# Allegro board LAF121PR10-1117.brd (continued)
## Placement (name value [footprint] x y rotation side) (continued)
Q7  -  [2N7002K_SOT23-3]  145.89 38.31 180 top
Q9  -  [2N7002K_SOT23-3]  51.47 63.15 0 top
Q10  -  [LMBT3904LT1G_SOT23-3]  111.67 112.87 180 bottom
Q11  L2N7002DW1T1G 2N  [DMN66D0LDW-7_SOT363-6]  180.99 65.15 0 top
Q14  L2N7002DW1T1G  [DMN66D0LDW-7_SOT363-6]  45.17 95.76 0 top
Q15  DDTA144VCA-7-F-GP  [2N7002K_SOT23-3]  48.33 97.98 270 top
Q16  DDTA144VCA-7-F-GP  [2N7002K_SOT23-3]  48.33 93.98 270 top
Q17  -  [2N7002KW_SOT323-3]  46.3 93.91 90 top
Q26  L2N7002DW1T1G  [DMN66D0LDW-7_SOT363-6]  42.17 90.75 90 top
QA1  -  [LN2306LT1G_SOT23-3]  37.75 15.4 0 top
QC1  -  [MESS138W-G_SOT323-3]  129.56 92.68 0 top
QC3  DMN63D8LDW-7  [2N7002KDWH_SOT363-6]  144.55 67.14 0 top
QC27  -  [2N7002K_SOT23-3]  140.65 33.71 90 bottom
QE1  2N7002KW 1N SOT323-3  [2N7002BKW_SOT323-3]  93.76 39.66 0 top
QI1  -  [2N7002K_SOT23-3]  23.69 100.26 270 top
QI2  -  [MMBT3904_NL_SOT23-3]  24.93 116.8 180 top
QI3  L2N7002DW1T1G  [DMN66D0LDW-7_SOT363-6]  13.81 109.67 270 bottom
QS1  L2N7002DW1T1G  [DMN66D0LDW-7_SOT363-6]  206.09 34.02 90 top
QT3  -  [2N7002K_SOT23-3]  33.82 113.51 180 bottom
QT4  -  [LN2306LT1G_SOT23-3]  32.55 115.35 0 top
QT5  -  [LN2306LT1G_SOT23-3]  37.82 113.57 180 bottom
QT6  L2N7002DW1T1G  [2N7002KDWH_SOT363-6]  31.29 123.78 180 bottom
QV1  L2N7002DW1T1G  [2N7002KDWH_SOT363-6]  123.66 120.85 0 top
QW1  DII-DMN65D8LW-7~D  [SSM3K7002FU_SC70-3]  83.66 118.74 90 top
R3  0_0402_5%  [R0402_0OHM]  210.8 54.61 180 bottom
R4  0_0402_5%  [R0402_0OHM]  210.68 56.89 180 bottom
R5  0_0805_5%  [R_0805]  203.18 57.97 0 top
R6  0_0402_5%  [R_0402]  210.8 56.13 180 bottom
R7  0_0402_5%  [R_0402-NPM]  215.57 43.68 180 top
R8  0_0402_5%  [R_0402-NPM]  215.57 44.57 180 top
R9  0_0603_5%  [R_0603]  214.33 31.75 180 top
R10  0_0402_5%  [R_0402]  116.89 27.36 180 top
R11  100K_0402_5%  [R_0402]  116.11 30.91 90 bottom
R12  0_0402_5%  [R_0402]  114.32 27.36 0 top
R13  4.7K_0402_5%  [R_0402]  41.44 85.29 90 top
R14  4.7K_0402_5%  [R_0402]  40.61 85.29 90 top
R15  0_0402_5%  [R_0402]  112.67 27.36 0 top
R16  100_0603_1%  [R_0603]  110.14 32.13 0 top
R17  20K_0402_1%  [R_0402]  105.32 29.35 270 top
R18  100K_0402_5%  [R_0402]  81.31 35.61 90 bottom
R19  1K_0402_5%  [R_0402]  80.49 36.52 270 bottom
R20  0_0402_5%  [R_0402]  82.14 36.52 270 bottom
R21  0_0402_5%  [R0402_0OHM]  82.97 35.61 90 bottom
R23  47K_0402_5%  [R_0402]  126.22 111.69 180 bottom
R24  0_0402_5%  [R0402_0OHM]  38.32 95.3 90 top
R26  0_0402_5%  [R0402_0OHM]  32.09 48.26 0 top
R27  1K_0402_5%  [R_0402]  32.09 47.43 0 top
R28  4.7K_0402_5%  [R_0402]  144.36 41.46 0 top
R30  100K_0402_5%  [R_0402]  52.93 67.1 90 top
R31  2.2K_0402_5%  [R_0402]  181.91 64.19 180 top
R32  2.2K_0402_5%  [R_0402]  181.38 68 0 top
R33  18.7K_0402_1%  [R_0402]  175.42 64.52 315 bottom
R34  2K_0402_1%  [R_0402]  178.84 61.02 315 bottom
R36  10K_0402_5%  [R_0402]  31.92 72.96 180 top
R56  0_0603_5%  [R_0603]  211.46 52.05 270 top
R58  10K_0402_5%  [R_0402]  211.68 52.94 90 top
R59  100K_0402_5%  [R_0402]  217.39 62.62 270 top
R61  100K_0402_5%  [R_0402]  218.22 62.62 270 top
R63  10K_0402_5%  [R_0402]  219.05 62.62 270 top
R64  100K_0402_5%  [R_0402]  219.87 62.62 270 top
R65  2.7K_0402_1%  [R_0402]  220.7 61.7 90 top
R68  200_0402_5%  [R_0402]  15.58 131.57 0 bottom
R69  200_0402_5%  [R_0402]  15.58 132.39 0 bottom
R82  100K_0402_5%  [R_0402]  39.07 91.96 270 top
R83  100K_0402_5%  [R_0402]  42.34 93.11 0 top
R300  10K_0402_5%  [R_0402]  208.94 34.02 90 top
R438  0_0402_5%  [R_0402]  126.96 111.69 0 bottom
R700  0_0603_5%  [R_0603]  223.36 33.08 180 bottom
R701  0_0603_5%  [R_0603]  223.36 34.35 180 bottom
R702  0_0402_5%  [R_0402]  146.22 34.48 180 top
R703  0_0402_5%  [R_0402]  32.09 46.6 0 top
R704  0_0402_5%  [R_0402]  32.09 49.08 0 top
R705  0_0402_5%  [R_0402]  37.5 95.3 90 top
R800  0_0402_5%  [R_0402]  43.25 91.31 90 top
R801  0_0603_5%  [R_0603]  210.21 52.05 270 top
RA2  0_0402_5%  [R0402_0OHM]  39.35 19.17 180 top
RA7  0_0402_5%  [R_0402]  39.35 20 180 top
RA8  10K_0402_5%  [R_0402]  30.18 8.69 0 top
RA10  100K_0402_5%  [R_0402]  29.8 17.65 0 top
RA12  0_0402_5%  [R_0402]  26.89 21.13 90 top
RA13  100K_0402_5%  [R_0402]  21.13 16.25 180 top
RA14  0_0402_5%  [R_0402]  33.38 16.06 180 top
RA19  22 +-5% 0402  [R_0402]  34.25 12.38 0 top
RA22  2.2K_0402_5%  [R_0402]  16.49 14.47 180 top
RA23  2.2K_0402_5%  [R_0402]  17.36 14.47 0 top
RA24  10_0402_1%  [R_0402]  20.94 11.43 180 top
RA25  1K_0402_5%  [R_0402]  22.7 20.49 90 top
RA26  4.7K_0402_5%  [R_0402]  20.94 12.19 180 top
RA27  10_0402_1%  [R_0402]  20.94 10.66 180 top
RA28  1K_0402_5%  [R_0402]  23.53 20.49 90 top
RA29  4.7K_0402_5%  [R_0402]  20.94 12.95 180 top
RA30  0_0402_5%  [R0402_0OHM]  9.8 19.24 0 top
RA31  10K_0402_5%  [R_0402]  17.29 19.24 0 bottom
RA32  10K_0402_5%  [R_0402]  16.43 19.24 180 bottom
RA38  0_0805_5%  [R0805_0OHM]  36.17 7.6 0 top
RA41  200K_0402_1%  [R_0402]  29.75 18.52 90 top
RA43  33_0402_5%  [R_0402]  32.41 14.09 0 top
RA44  0_0402_5%  [R_0402]  32.41 13.27 0 top
RA45  10K_0402_5%  [R_0402]  28.55 22.04 270 top
RA49  1K_0402_1%  [R_0402]  29.37 21.13 90 top
RA51  0_0805_5%  [R0805_0OHM]  21.37 22.88 270 top
RA52  0_0603_5%  [R0603_0OHM]  19.91 22.28 270 top
RA53  0_0402_5%  [R0402_0OHM]  37.7 19.17 180 top
RA54  0_0402_5%  [R_0402]  27.72 22.04 270 top
RA55  33_0402_5%  [R_0402]  35.16 10.54 180 top
RA56  0_0402_5%  [R_0402]  34.32 15.73 90 top
RA57  0_0603_5%  [R_0603]  12.48 19.17 0 top
RA58  0_0402_5%  [R_0402]  36.79 20 0 top
RC1  1K_0402_5%  [R_0402]  100.67 64.96 0 top
RC2  1K_0402_5%  [R_0402]  120.89 68.45 180 top
RC3  2.2K_0402_5%  [R_0402]  129.51 93.84 90 top
RC4  4.7K_0402_5%  [R_0402]  131.94 96.2 180 top
RC5  4.7K_0402_5%  [R_0402]  210.79 47.99 90 top
RC6  1K_0402_5%  [R_0402]  124.56 91.32 270 top
RC7  1K_0402_5%  [R_0402]  126.21 91.32 270 top
RC8  1K_0402_5%  [R_0402]  125.38 91.32 270 top
RC10  1K_0402_5%  [R_0402]  128.69 88.25 90 top
RC12  300_0402_5%  [R_0402]  145.14 56.45 180 bottom
RC13  196_0402_1%  [R_0402]  144.36 73.85 0 top
RC15  300_0402_5%  [R_0402]  148.55 60.83 0 top
RC16  1K_0402_5%  [R_0402]  129.51 88.25 90 top
RC17  10K_0402_5%  [R_0402]  130.21 48.84 270 top
RC18  0_0402_5%  [R_0402]  126.21 89.16 270 top
RC19  0_0402_5%  [R_0402]  123.73 89.16 270 top
RC20  0_0402_5%  [R_0402]  125.38 89.16 270 top
RC22  0_0402_5%  [R_0402]  124.56 89.16 270 top
RC24  1K_0402_5%  [R_0402]  127.73 91.32 270 top
RC25  1K_0402_5%  [R_0402]  126.97 91.32 270 top
RC26  1K_0402_5%  [R_0402]  123.73 91.32 270 top
RC27  220_0402_5%  [R_0402]  148.55 60.07 0 top
RC28  0_0402_5%  [R_0402]  46.14 85.29 90 top
RC29  33_0402_5%  [R_0402]  106.84 117.55 270 bottom
RC30  0_0402_5%  [R_0402]  49.12 65.54 270 top
RC33  4.7K_0402_5%  [R_0402]  132.88 47.93 90 top
RC34  4.7K_0402_5%  [R_0402]  131.99 45.51 90 top
RC36  0_0402_5%  [R_0402]  130.96 45.52 0 bottom
RC39  0_0402_5%  [R0402_0OHM]  42.39 65.54 270 top
RC40  10K_0402_5%  [R_0402]  128.44 47.93 90 top
RC41  10K_0402_5%  [R_0402]  131.99 48.84 270 top
RC42  10K_0402_5%  [R_0402]  131.1 45.51 90 top
RC44  0_0402_5%  [R_0402]  108.29 121.03 0 bottom
RC46  10K_0402_5%  [R_0402]  125.76 43.23 90 top
RC47  10K_0402_5%  [R_0402]  118.72 45.78 0 top
RC48  10K_0402_5%  [R_0402]  144.36 56.38 0 top
RC49  0_0402_5%  [R_0402]  110.71 119.39 270 bottom
RC51  2K_0402_5%  [R_0402]  120.7 38.54 180 bottom
RC52  2K_0402_5%  [R_0402]  144.36 58.16 0 top
RC53  10K_0402_5%  [R_0402]  124.88 43.23 90 top
RC54  22K_0402_5%  [R_0402]  119.92 47.67 90 top
RC56  10K_0402_5%  [R_0402]  148.55 62.48 0 top
RC57  10K_0402_5%  [R_0402]  148.55 61.65 0 top
RC58  10K_0402_5%  [R_0402]  144.76 61.91 180 bottom
RC59  10K_0402_5%  [R_0402]  144.76 62.73 180 bottom
RC60  10K_0402_5%  [R_0402]  131.91 60.64 0 top
RC61  10K_0402_5%  [R_0402]  118.83 51.18 0 top
RC62  10K_0402_5%  [R_0402]  149.47 55.75 180 top
RC74  10_0402_1%  [R_0402]  119.78 39.43 0 bottom
RC94  4.7K_0402_5%  [R_0402]  145.06 69.85 0 top
RC95  4.7K_0402_5%  [R_0402]  145.27 66.04 180 top
RC96  0_0402_5%  [R0402_0OHM]  123.19 47.93 90 top
RC97  0_0402_5%  [R_0402]  145.27 61.91 180 top
RC98  1K_0402_5%  [R_0402]  133.02 33.4 180 bottom
RC99  1K_0402_5%  [R_0402]  161.93 29.85 270 top
RC102  0_0402_5%  [R_0402]  212.9 59.49 180 top
RC103  0_0402_5%  [R_0402]  212.9 60.32 180 top
RC104  1M_0402_5%  [R_0402]  218.61 50.03 180 top
RC449  22_0402_5%  [R_0402]  125.5 45.58 0 bottom
RC602  33_0402_5%  [R_0402]  126.65 43.23 90 top
RC615  10K_0402_5%  [R_0402]  123.99 47.93 90 top
RC616  0_0402_5%  [R_0402]  127.86 89.16 270 top
RC617  0_0402_5%  [R_0402]  127.03 89.16 270 top
RC618  0_0402_5%  [R_0402]  130.96 44.7 0 bottom
RC619  10K_0402_5%  [R_0402]  144.36 62.73 0 top
RC620  10K_0402_5%  [R_0402]  145.27 63.56 180 top
RC621  10K_0402_5%  [R_0402]  127.47 47.93 90 top
RC622  10K_0402_5%  [R_0402]  121.33 45.78 180 top
RC630  0_0402_5%  [R_0402]  43.21 64.63 90 top
RC631  0_0402_5%  [R_0402]  130.96 43.87 0 bottom
RC639  10K_0402_5%  [R_0402]  131.86 40.37 90 bottom
RC640  10K_0402_5%  [R_0402]  131.92 37.47 270 bottom
RC642  10K_0402_5%  [R_0402]  120.7 40.32 180 bottom
RC646  10K_0402_5%  [R_0402]  130.21 46.43 270 top
RC661  0_0402_5%  [R_0402]  131.75 43.05 180 bottom
RC663  10K_0402_5%  [R_0402]  133.7 47.93 90 top
RC664  1K_0402_5%  [R_0402]  126.65 47.93 90 top
RC680  10_0402_5%  [R_0402]  119.78 37.18 0 bottom
RC681  100K_0402_5%  [R_0402]  127.54 44.14 270 top
RC700  0_0402_5%  [R_0402]  107.67 116.63 90 bottom
RC701  0_0402_5%  [R_0402]  109.32 116.63 90 bottom
RC703  10K_0402_5%  [R_0402]  108.49 116.63 90 bottom
RC704  33_0402_5%  [R_0402]  110.14 116.63 90 bottom
RC711  10K_0402_5%  [R_0402]  129.41 45.51 90 top
RC712  10K_0402_5%  [R_0402]  129.32 48.84 270 top
RC801  10M_0402_5%  [R_0402]  144.45 32.44 90 bottom
RC902  0_0402_5%  [R_0402]  122.55 53.42 90 top
RC905  100K_0402_5%  [R_0402]  145.27 65.18 180 top
RC906  100K_0402_5%  [R_0402]  147.28 64.38 0 top
RC914  20M_0402_5%  [R_0402]  143.54 53.01 90 bottom
RC938  10K_0402_5%  [R_0402]  124.88 47.93 90 top
RC939  1M_0402_5%  [R_0402]  143.61 48.18 90 bottom
RC1672  0_0603_5%  [R_0603]  118.91 44.64 0 top
RC1689  22 +-5% 0402  [R_0402]  127.54 55.06 270 top
RC1695  10K_0402_5%  [R_0402]  124.88 45.51 90 top
RC1696  10K_0402_5%  [R_0402]  125.76 47.93 90 top
RC1697  10K_0402_5%  [R_0402]  125.76 45.51 90 top
RC1700  0_0603_5%  [R_0603]  122.72 44.53 180 top
RC1706  10K_0402_5%  [R_0402]  120.7 35.36 180 bottom
RC1707  10K_0402_5%  [R_0402]  131.87 46.35 180 bottom
RC6121  100K_0402_5%  [R_0402]  145.27 64.38 180 top
RC6122  10K_0402_5%  [R_0402]  131.1 47.93 90 top
RC6123  10K_0402_5%  [R_0402]  120.7 41.21 180 bottom
RC6124  10K_0402_5%  [R_0402]  126.65 46.43 270 top
RC6125  0_0402_5%  [R_0402]  144.83 66.8 180 bottom
RC6126  0_0402_5%  [R_0402]  136.05 27.19 270 bottom
RC6127  10K_0402_5%  [R_0402]  135.1 26.27 90 bottom
RC6128  0_0402_5%  [R0402_0OHM]  126.4 62.16 0 top
RC6129  0_0402_5%  [R0402_0OHM]  123.95 61.58 90 top
RC6130  10K_0402_5%  [R_0402]  142.5 36.1 180 bottom
RD1  1K_0402_1%  [R_0402]  73.05 67.24 0 top
RD2  1K_0402_1%  [R_0402]  70.76 67.24 0 top
RD3  1K_0402_1%  [R_0402]  60.3 67.29 90 top
RD4  1K_0402_1%  [R_0402]  58.06 67.24 0 top
RE1  0_0805_5%  [R_0805]  92.34 36.25 0 top
RE2  10K_0402_5%  [R_0402]  91.99 39.05 180 top
RE3  100K_0402_5%  [R_0402]  91.99 38.22 180 top
RE4  240_0402_1%  [R_0402]  56.57 34.6 0 bottom
RE5  100K_0402_1%  [R_0402]  51.28 85.29 90 top
RE6  0_0603_5%  [R_0603]  35.15 85.47 180 top
RE8  100K_0402_1%  [R_0402]  33.64 83.36 180 top
RE9  0_0402_1%  [R_0402]  49.56 86.2 270 top
RE11  0_0402_1%  [R_0402]  32.72 82.58 0 top
RE12  0_0402_5%  [R_0402]  32.72 76.26 0 top
RE14  33_0402_5%  [R_0402]  41.18 65.54 270 top
RE17  10K_0402_5%  [R_0402]  33.64 74.63 180 top
RE18  10K_0402_5%  [R_0402]  42.26 85.29 90 top
RE19  10K_0402_5%  [R_0402]  39.79 86.2 270 top
RE23  10K_0402_5%  [R_0402]  47.47 64.63 90 top
RE24  10K_0402_5%  [R_0402]  32.72 84.13 0 top
RE25  10K_0402_5%  [R_0402]  44.04 64.63 90 top
RE30  0_0402_5%  [R0402_0OHM]  39.4 64.63 90 top
RE31  10K_0402_5%  [R_0402]  33.64 81.66 180 top
RE35  0_0402_5%  [R0402_0OHM]  33.64 78.1 180 top
RE36  0_0402_5%  [R0402_0OHM]  48.74 85.29 90 top
RE37  0_0402_5%  [R_0402]  46.64 64.63 90 top
RE39  0_0402_5%  [R_0402]  32.72 72.96 0 top
RE40  0_0402_5%  [R_0402]  32.72 69.65 0 top
RE41  0_0402_5%  [R_0402]  33.64 73.78 180 top
RE42  0_0402_5%  [R_0402]  32.72 70.48 0 top
RE43  0_0402_5%  [R0402_0OHM]  33.64 78.93 180 top
RE44  100K_0402_5%  [R_0402]  32.72 75.43 0 top
RE50  0_0402_5%  [R0402_0OHM]  32.72 71.31 0 top
RE52  0_0402_5%  [R0402_0OHM]  54.21 71.69 180 top
RE506  2.2K_0402_5%  [R_0402]  33.64 79.88 180 top
RE507  10K_0402_5%  [R_0402]  33.64 72.13 180 top
RE508  0_0603_5%  [R_0603]  35.15 86.74 180 top
RE509  2.2K_0402_5%  [R_0402]  44.48 86.2 270 top
RE510  2.2K_0402_5%  [R_0402]  45.31 86.2 270 top
RF1  10K_0402_5%  [R_0402]  45.82 65.54 270 top
RF2  10K_0402_5%  [R_0402]  180.56 68.82 45 top
RF3  10K_0402_5%  [R_0402]  180.63 70.04 225 top
RH21  33_0402_5%  [R_0402]  226.3 59.94 180 top
RH22  10K_0402_5%  [R_0402]  226.3 60.7 180 top
RH23  10K_0402_5%  [R_0402]  226.3 61.53 180 top
RH24  10K_0402_5%  [R_0402]  226.3 62.35 180 top
RH25  33_0402_5%  [R_0402]  224.77 67.56 180 top
RH26  1K_0402_5%  [R_0402]  226.3 59.11 180 top
RH27  0_0402_5%  [R_0402]  223.54 63.56 180 top
RH28  0_0402_5%  [R_0402]  219.48 64.45 90 top
RI1  0_0402_5%  [R_0402-NPM]  17.26 94.29 180 top
RI2  150_0402_5%  [R_0402]  14.92 94.35 270 top
RI3  0_0402_5%  [R_0402-NPM]  17.26 93.4 180 top
RI4  0_0402_5%  [R_0402-NPM]  17.26 96.13 180 top
RI6  150_0402_5%  [R_0402]  14.92 96.26 270 top
RI7  0_0402_5%  [R_0402-NPM]  17.26 95.25 180 top
RI8  0_0402_5%  [R_0402-NPM]  17.26 92.58 180 top
RI9  150_0402_5%  [R_0402]  14.92 92.64 270 top
RI10  0_0402_5%  [R_0402-NPM]  17.26 91.69 180 top
RI12  0_0402_5%  [R_0402-NPM]  17.26 89.59 180 top
RI13  150_0402_5%  [R_0402]  14.92 89.63 90 top
RI14  0_0402_5%  [R_0402-NPM]  17.26 90.48 180 top
RI15  150K_0402_5%  [R_0402]  23.4 113.04 270 top
RI16  20K_0402_5%  [R_0402]  16.8 106.47 90 top
RI17  100K_0402_5%  [R_0402]  24.23 113.04 270 top
RI20  100K_0402_5%  [R_0402]  27.53 99.74 90 top
RI21  499_0402_1%  [R_0402]  20.91 97.09 0 top
RI22  499_0402_1%  [R_0402]  20.91 94.42 0 top
RI23  499_0402_1%  [R_0402]  18.56 95.25 0 top
RI24  499_0402_1%  [R_0402]  18.56 92.58 0 top
RI25  499_0402_1%  [R_0402]  18.56 88.64 0 top
RI26  499_0402_1%  [R_0402]  18.56 91.31 0 top
RI27  499_0402_1%  [R_0402]  20.91 90.67 0 top
RI28  499_0402_1%  [R_0402]  20.91 93.34 0 top
RL1  10K_0402_5%  [R_0402]  31.39 91.12 0 top
RL2  100K_0402_5%  [R_0402]  27.77 89.4 0 top
RL3  0_0603_5%  [R_0603]  21.94 86.61 90 bottom
RL4  0_0402_5%  [R_0402]  24.35 87.7 270 top
RL5  0_0402_5%  [R_0402]  25.18 87.7 270 top
RL6  10K_0402_5%  [R_0402]  28.69 87.75 180 top
RL7  75_0603_5%  [R_0603]  18.91 75.94 90 top
RL8  2.49K_0402_1%~D  [R_0402]  17.99 80.51 0 top
RL9  75_0603_5%  [R_0603]  16.49 75.94 90 top
RL10  10K_0402_5%  [R_0402]  21.88 87.7 270 top
RL12  1K_0402_5%  [R_0402]  22.7 87.7 270 top
RL14  15K_0402_1%  [R_0402]  23.53 86.79 90 top
RL15  10K_0402_5%  [R_0402]  27.77 82.29 0 top
RL16  10K_0402_5%  [R_0402]  28.69 90.23 180 top
RL17  0_0402_5%  [R_0402]  28.69 88.58 180 top
RL18  0_0603_5%  [R_0603]  20.54 84.6 270 bottom
RL19  75_0603_5%  [R_0603]  20.11 75.94 90 top
RL20  75_0603_5%  [R_0603]  17.7 75.94 90 top
RM1  0_1206_5%  [R_1206]  80.3 119.82 180 top
RP1  100K_0402_5%  [R_0402]  210.8 55.37 180 bottom
RP2  10K_0402_5%  [R_0402]  211.92 47.18 0 top
RP3  1M +-5% 0402  [R_0402]  211.92 48 0 top
RP4  2.2K_0804_8P4R_5%  [RP_0804_8P4R]  119.81 27.74 90 top
RP5  100K_0402_5%  [R_0402]  216.18 32.99 180 top
RPC1  100K_0804_8P4R_5%  [RP_0804_8P4R]  132.82 90.81 180 top
RPC3  1K_0804_8P4R_5%  [RP_0804_8P4R]  125.84 94.04 90 top
RPC4  33_0804_8P4R_5%  [RP_0804_8P4R]  145.96 59.32 180 top
RPC5  1K_0804_8P4R_5%  [RP_0804_8P4R]  145.26 60.82 180 bottom
RPC30  10K_0804_8P4R_5%  [RP_0804_8P4R]  124.21 95.21 270 top
RPC64  2.2K_0804_8P4R_5%  [RP_0804_8P4R]  200.52 31.42 90 top
RPH1  1K_0804_8P4R_5%  [RP_0804_8P4R]  222.87 65.02 90 top
RPI3  2.2K_0804_8P4R_5%  [RP_0804_8P4R]  13.67 111.18 90 bottom
RPV34  10K_8P4R_5%  [RP_0804_8P4R]  129.43 115.31 90 bottom
RS3  4.7K_0402_5%  [R_0402]  179.03 31.17 0 top
RS4  4.7K_0402_5%  [R_0402]  186.66 37.26 90 top
RS5  0_0402_5%  [R_0402]  190.39 30.54 0 top
RS6  0_0402_5%  [R_0402]  180.56 38.17 270 top
RS7  0_0402_5%  [R_0402]  189.09 30.54 180 top
RS8  0_0402_5%  [R_0402]  179.94 30.35 180 top
RS9  0_0402_5%  [R_0402]  179.94 29.52 180 top
RS10  0_0402_5%  [R_0402]  185.9 38.17 270 top
RS11  0_0402_5%  [R_0402]  182.85 38.17 270 top
RS12  0_0402_5%  [R_0402]  183.61 38.17 270 top
RS13  0_0402_5%  [R_0402]  184.37 38.17 270 top
RS15  0_0402_5%  [R_0402]  187.42 37.26 90 bottom
RS16  0_0402_5%  [R_0402]  188.18 37.26 90 bottom
RS17  4.7K_0402_5%  [R_0402]  177.96 30.08 90 top
RS18  4.7K_0402_5%  [R_0402]  187.42 37.26 90 top
RS19  0_0402_5%  [R_0402]  177.96 29.28 270 top
RS20  0_0402_5%  [R_0402]  185.14 37.26 90 top
RS21  0_0402_5%  [R_0402]  182.09 37.26 90 top
RS22  0_0402_5%  [R_0402]  178.29 34.98 180 top
RS23  2K_0402_5%  [R_0402]  192.36 30.54 0 top
RS24  5.1K_0402_1%  [R_0402]  181.33 37.26 90 top
RS25  0_0402_5%  [R_0402]  178.29 34.16 180 top
RS26  0_0402_5%  [R_0402]  178.29 32.32 180 top
RS27  0_0402_5%  [R_0402]  178.29 33.14 180 top
RS28  100K_0402_5%  [R_0402]  185.9 38.17 270 bottom
RS29  100K_0402_5%  [R_0402]  203.23 33.7 90 top
RS60  10K_0402_5%  [R_0402]  188.25 35.11 90 top
RS61  0_0402_5%  [R_0402]  186.66 38.17 270 bottom
RS62  0_0402_5%  [R_0402]  43.24 89.58 90 top
RS63  0_0402_5%  [R_0402]  25.51 25.22 270 top
RT1  100K_0402_1%  [R_0402]  37.37 117.52 90 bottom
RT2  10K_0402_5%  [R_0402]  18.13 119.55 90 top
RT3  10K_0402_1%  [R_0402]  35.92 119.69 180 top
RT4  10K_0402_5%  [R_0402]  30.5 118.68 0 bottom
RT6  4.7K_0402_5%  [R_0402]  39.01 112.96 0 top
RT9  0_0402_5%  [R_0402-NPM]  23.35 130.81 180 bottom
RT10  0_0402_5%  [R_0402-NPM]  23.35 131.69 180 bottom
RT17  1K_0402_5%  [R_0402]  25.19 122.04 180 top
RT18  1K_0402_5%  [R_0402]  17.69 128.28 270 bottom
RT19  1K_0402_5%  [R_0402]  16.48 125.8 270 top
RT20  1K_0402_5%  [R_0402]  21.23 116.7 90 bottom
RT21  1K_0402_5%  [R_0402]  19.21 128.28 270 bottom
RT22  1K_0402_5%  [R_0402]  18.45 128.28 270 bottom
RT23  1K_0402_5%  [R_0402]  25.19 122.93 180 top
RT24  1K_0402_5%  [R_0402]  16.91 116.7 90 bottom
RT25  1K_0402_5%  [R_0402]  17.24 125.8 270 top
RT26  1K_0402_5%  [R_0402]  19.97 128.28 270 bottom
RT27  1K_0402_5%  [R_0402]  25.19 123.82 180 top
RT28  1K_0402_5%  [R_0402]  21.5 128.28 270 bottom
RT29  1K_0402_5%  [R_0402]  22.88 116.7 90 bottom
RT30  1K_0402_5%  [R_0402]  22.06 116.7 90 bottom
RT31  10K_0402_5%  [R_0402]  20.74 127.36 90 bottom
RT32  100K_0402_5%  [R_0402]  33.23 117.28 0 bottom
RT33  100_1206_5%  [R_1206]  30.83 116.26 270 bottom
RT34  2M_0402_1%  [R_0402]  19.78 120.47 270 top
RT35  100K_0402_5%  [R_0402]  17.74 116.7 90 bottom
RT36  4.7K_0402_5%  [R_0402]  30.5 122.74 0 bottom
RT37  4.7K_0402_5%  [R_0402]  30.72 126.42 180 bottom
RT40  0_0402_5%  [R_0402]  21.89 121.6 180 top
RT41  0_0402_5%  [R_0402]  18 125.8 270 top
RT42  0_0402_5%  [R_0402]  17.48 122.87 0 top
RT43  0_0402_5%  [R_0402]  21.31 119.55 90 top
RT44  0_0402_5%  [R_0402]  19.53 125.8 270 top
RT45  0_0402_5%  [R_0402]  18.77 125.8 270 top
RT46  0_0402_5%  [R_0402]  21.89 122.8 180 top
RT47  0_0402_5%  [R_0402]  17.48 121.28 0 top
RT48  0_0402_5%  [R_0402]  17.48 123.88 0 top
RT49  0_0402_5%  [R_0402]  20.29 125.8 270 top
RT50  0_0402_5%  [R_0402]  21.89 124.01 180 top
RT51  0_0402_5%  [R_0402]  21.81 125.8 270 top
RT52  0_0402_5%  [R_0402]  22.83 119.55 90 top
RT53  0_0402_5%  [R_0402]  22.07 119.55 90 top
RT54  0_0402_5%  [R_0402]  30.5 121.98 0 bottom
RT55  0_0402_5%  [R_0402]  28.04 125.83 270 bottom
RT60  2M_0402_1%  [R_0402]  20.54 120.47 270 top
RT61  0_0402_5%  [R_0402]  21.05 125.8 270 top
RT62  10K_0402_5%  [R_0402]  34.36 132.18 180 top
RT63  100K_0402_5%  [R_0402]  36.29 112.71 180 bottom
RT64  20K_0402_5%  [R_0402]  30.5 121.15 0 bottom
RT65  10K_0402_5%  [R_0402]  31.42 120.33 180 bottom
RT70  2.2K_0402_5%  [R_0402]  30.31 125.22 0 top
RT71  2.2K_0402_5%  [R_0402]  31.16 123.82 180 top
RT72  2.2K_0402_5%  [R_0402]  35.47 117.52 90 bottom
RT73  2.2K_0402_5%  [R_0402]  36.29 117.52 90 bottom
RT101  100K_0402_5%  [R_0402]  20.4 116.7 90 bottom
RT102  0_0402_5%  [R_0402-NPM]  23.35 129.09 180 bottom
RT103  0_0402_5%  [R_0402-NPM]  23.35 129.98 180 bottom
RT104  0_0402_5%  [R_0402-NPM]  12.24 123.82 180 top
RT105  0_0402_5%  [R_0402-NPM]  12.24 122.93 180 top
RT106  0_0402_5%  [R_0402-NPM]  13.51 118.11 180 top
RT107  0_0402_5%  [R_0402-NPM]  13.51 117.22 180 top
RT108  0_0402_5%  [R_0402-NPM]  13.23 126.23 0 top
RT109  0_0402_5%  [R_0402-NPM]  13.23 125.34 0 top
RT110  0_0402_5%  [R_0402-NPM]  11.64 119.18 0 top
RT111  0_0402_5%  [R_0402-NPM]  11.64 120.07 0 top
RT112  200K_0402_1%  [R_0402]  27.59 114.12 270 top
RT113  0_0402_5%  [R_0402]  34.96 116.4 270 top
RT115  10K_0402_5%  [R_0402]  31.42 119.5 180 bottom
RT116  10K_0402_5%  [R_0402]  18.4 122.04 180 top
RT117  100K_0402_1%  [R_0402]  39.02 118.44 270 bottom
RT118  100K_0402_1%  [R_0402]  38.2 118.44 270 bottom
RT119  10K_0402_5%  [R_0402]  30.32 131.05 90 bottom
RT130  0_0402_5%  [R_0402]  28.15 128.01 0 bottom
RT131  0_0402_5%  [R_0402]  18.64 117.67 270 top
RT132  0_0402_5%  [R_0402]  21 115.81 0 bottom
RT133  0_0402_5%  [R_0402]  21 114.99 0 bottom
RT134  2.2K_0402_5%  [R_0402]  27.71 119.01 90 top
RU1  0_0402_5%  [R_0402-NPM]  22.53 58.29 180 top
RU2  0_0402_5%  [R_0402-NPM]  22.53 57.4 180 top
RU3  0_0402_5%  [R_0402-NPM]  22.53 59.11 180 top
RU4  0_0402_5%  [R_0402-NPM]  22.53 60 180 top
RU5  0_0402_5%  [R_0402-NPM]  32.37 57.08 180 top
RU6  0_0402_5%  [R_0402-NPM]  32.37 57.97 180 top
RU7  0_0402_5%  [R_0402-NPM]  20.99 37.41 270 top
RU8  0_0402_5%  [R_0402-NPM]  20.1 37.41 270 top
RU9  0_0402_5%  [R_0402-NPM]  19.27 37.41 270 top
RU10  0_0402_5%  [R_0402-NPM]  18.39 37.41 270 top
RU11  0_0402_5%  [R_0402-NPM]  32.56 39.05 180 bottom
RU12  0_0402_5%  [R_0402-NPM]  32.56 39.94 180 bottom
RU13  0_0402_5%  [R_0402-NPM]  210.69 33.94 90 top
RU14  0_0402_5%  [R_0402-NPM]  209.87 33.94 90 top
RU15  0_0402_5%  [R_0402-NPM]  208.03 33.91 90 top
RU16  0_0402_5%  [R_0402-NPM]  207.27 33.91 90 top
RV1  1.69K_0402_1%  [R_0402]  121.25 139.12 90 top
RV2  1K_0402_1%  [R_0402]  124.57 128.43 0 top
RV3  1K_0402_1%  [R_0402]  120.17 139.12 90 top
RV4  100K_0402_5%  [R_0402]  109.77 140.19 180 bottom
RV5  45.3K_0402_1%  [R_0402]  124.04 123.68 0 top
RV6  45.3K_0402_1%  [R_0402]  122.66 119.67 90 top
RV8  8.45K_0402_1%  [R_0402]  115.68 134.27 90 top
RV9  2K_0402_1%  [R_0402]  116.58 135.17 270 top
RV11  8.45K_0402_1%  [R_0402]  113.89 136.61 270 top
RV12  2K_0402_1%  [R_0402]  114.78 135.71 90 top
RV13  4.75K_0402_1%  [R_0402]  113.89 133.91 90 top
RV15  8.45K_0402_1%  [R_0402]  113.08 139.57 0 top
RV16  4.75K_0402_1%  [R_0402]  114.33 138.67 180 top
RV17  1K_0402_1%  [R_0402]  128.64 120.43 90 top
RV21  10K_0402_5%  [R_0402]  123.93 117.7 90 bottom
RV24  1M_0402_5%  [R_0402]  109.7 144.03 270 bottom
RV27  0_0603_5%  [R0603_0OHM]  111.64 129.33 0 top
RV28  8.45K_0402_1%  [R_0402]  112.81 134.81 270 top
RV29  10K_0402_5%  [R_0402]  118.12 139.79 270 top
RV30  0_0603_5%  [R0603_0OHM]  112.54 128.08 0 top
RV31  0_0603_5%  [R0603_0OHM]  120.29 143.27 0 top
RV32  40.2_0402_1%  [R_0402]  140 147.25 180 top
RV33  40.2_0402_1%  [R_0402]  140 148.08 180 top
RV34  100_0402_1%  [R_0402]  139.04 148.89 90 top
RV35  100_0402_1%  [R_0402]  139.04 146.44 270 top
RV36  49.9_0402_1%  [R_0402]  150.05 116.58 270 bottom
RV37  10_0402_1%  [R_0402]  149.29 116.58 270 bottom
RV38  5.1K_0402_1%  [R_0402]  148.53 116.58 270 bottom
RV39  120_0402_1%  [R_0402]  121.7 145.4 0 top
RV40  51.1_0402_1%  [R_0402]  129.71 119.1 90 top
RV41  51.1_0402_1%  [R_0402]  128.61 119.18 180 top
RV48  2.37K_0402_1%  [R_0402]  164.25 120.95 90 top
RV49  5.49K_0402_1%  [R_0402]  164.24 122.74 0 top
RV50  2.37K_0402_1%  [R_0402]  155.49 115.74 90 bottom
RV51  5.49K_0402_1%  [R_0402]  153.71 116.65 270 bottom
RV52  2.37K_0402_1%  [R_0402]  164.06 146.24 270 top
RV53  5.49K_0402_1%  [R_0402]  163.98 143.5 0 top
RV54  2.37K_0402_1%  [R_0402]  153.62 149.06 90 bottom
RV55  5.49K_0402_1%  [R_0402]  154.64 149.92 0 bottom
RV59  10K_0402_5%  [R_0402]  119.18 140.03 270 top
RV71  0_0402_5%  [R_0402]  107.35 127.11 90 bottom
RV79  120_0402_1%  [R_0402]  154.64 149.96 270 top
RV80  120_0402_1%  [R_0402]  155.53 149.96 270 top
RV81  4.7K_0402_5%  [R_0402]  121.07 119.36 270 bottom
RV82  4.7K_0402_5%  [R_0402]  121.97 119.36 270 bottom
RV83  16.2K_0402_1%  [R_0402]  120.17 119.36 270 bottom
RV84  10K_0402_5%  [R_0402]  109.08 127.11 180 bottom
RV85  120_0402_1%  [R_0402]  155.49 115.74 90 top
RV86  120_0402_1%  [R_0402]  154.6 115.74 90 top
RV87  10K_0402_5%  [R_0402]  109.07 128.01 180 bottom
RV88  10K_0402_5%  [R_0402]  108.13 128.91 0 bottom
RV89  10K_0402_5%  [R_0402]  110.74 127.11 180 bottom
RV116  1K_0402_1%  [R_0402]  155.09 132.45 0 top
RV117  1K_0402_1%  [R_0402]  155.09 132.45 0 bottom
RV118  1K_0402_1%  [R_0402]  164.24 123.62 0 top
RV119  1K_0402_1%  [R_0402]  164.24 123.62 0 bottom
RV120  121_0402_1%  [R_0402]  153.71 116.65 270 top
RV121  121_0402_1%  [R_0402]  152.82 116.65 270 bottom
RV123  121_0402_1%  [R_0402]  153.83 149.05 90 top
RV131  1K_0402_1%  [R_0402]  155.09 133.4 0 bottom
RV132  121_0402_1%  [R_0402]  157.27 149.03 180 bottom
RV133  1K_0402_1%  [R_0402]  163.98 142.55 0 bottom
RV134  1K_0402_1%  [R_0402]  155.09 133.4 0 top
RV135  1K_0402_1%  [R_0402]  163.98 142.55 0 top
RV150  0_0402_5%  [R_0402]  50.33 89.04 270 top
RV151  10K_0402_5%  [R_0402]  127.27 118.56 90 bottom
RV152  10K_0402_5%  [R_0402]  125.83 119.45 270 bottom
RV153  0_0402_5%  [R_0402]  124.88 118.47 90 bottom
RV154  5.1K_0402_1%  [R_0402]  127.74 120.43 90 top
RV155  0_0402_5%  [R_0402]  110.74 130.1 180 bottom
RV156  0_0402_5%  [R_0402]  110.68 129.23 180 bottom
RV157  0_0402_5%  [R_0402]  110.74 128.33 180 bottom
RV158  0_0402_5%  [R_0402]  116.31 139.05 270 top
RV159  0_0402_5%  [R_0402]  117.21 139.05 270 top
RV162  4.7K_0402_5%  [R_0402]  108.85 138.49 0 bottom
RV163  4.7K_0402_5%  [R_0402]  109.76 139.39 180 bottom
RV164  0_0402_5%  [R_0402]  48.69 91.44 180 top
RV165  0_0402_5%  [R_0402]  47.77 90.61 0 top
RV260  4.7K_0402_5%  [R_0402]  130.72 115.3 90 bottom
RV364  0_0603_5%  [R0603_0OHM]  116.19 117.25 0 bottom
RV368  10K_0402_5%  [R_0402]  124.93 120.32 0 bottom
RV369  10K_0402_5%  [R_0402]  126.03 119.16 90 top
RW2  0_0603_5%  [R0603_0OHM]  214.28 47.05 0 top
RW3  0_0603_5%  [R0603_0OHM]  216.06 29.74 180 top
RW4  0_0603_5%  [R0603_0OHM]  213.01 40.25 180 top
RW6  0_0402_5%  [R_0402]  68.36 117.08 90 bottom
RW7  0_0402_5%  [R_0402]  48.29 65.54 270 top
RW8  10K_0402_5%~D  [R_0402]  79.65 118.36 0 top
RW10  0_0402_5%  [R_0402]  69.25 117.08 90 bottom
RW11  0_0402_5%  [R_0402]  70.01 117.99 270 bottom
RW12  100K_0402_5%  [R_0402]  67.53 117.99 270 bottom
RW13  10K_0402_5%  [R_0402]  72.17 138.73 90 top
RW14  100K_0402_5%  [R_0402]  67.73 138.73 90 top
RW15  0_0402_5%  [R_0402]  79.47 133.08 90 top
RX1  0_0201_5%  [R_0201]  131.66 39.2 270 bottom
RX2  0_0201_5%  [R_0201]  120.57 34.56 180 bottom
RX3  0_0201_5%  [R_0201]  107.7 39.11 180 bottom
RX4  0_0201_5%  [R_0201]  120.58 37.87 180 bottom
RX5  0_0201_5%  [R_0201]  107.7 36.25 180 bottom
RX6  0_0201_5%  [R_0201]  106.07 31.17 180 bottom
RX7  10K_0402_5%  [R_0402]  223.06 43.14 90 top
RX8  0_0402_5%  [R_0402]  217.8 44.93 270 top
RX9  0_0402_5%  [R_0402]  218.61 44.93 270 top
RX13  10K_0402_5%  [R_0402]  105.01 39.19 270 top
RX14  10K_0402_5%  [R_0402]  104.24 39.19 270 top
RX15  100_0402_5%  [R_0402]  209.76 57.65 0 bottom
RX16  10K_0402_5%  [R_0402]  105.77 39.19 270 top
RX25  33_0402_5%  [R_0402]  212.84 42.29 180 top
RX26  0_0603_5%  [R_0603]  110.33 34.16 180 bottom
RX27  0_0603_5%  [R_0603]  110.33 32.89 180 bottom
RX28  0_0201_5%  [R_0201]  98.65 36.48 270 bottom
RX29  0_0201_5%  [R_0201]  108 33.47 180 bottom
RX30  0_0201_5%  [R_0201]  107.7 35.68 180 bottom
RX31  0_0201_5%  [R_0201]  107.7 38.54 180 bottom
RX32  0_0201_5%  [R_0201]  101.41 40.32 0 bottom
RX33  0_0201_5%  [R_0201]  107.7 37.97 180 bottom
RX34  0_0201_5%  [R_0201]  107.7 36.83 180 bottom
RX35  0_0201_5%  [R_0201]  104.53 32.32 180 bottom
RX36  0_0201_5%  [R_0201]  101.41 39.75 0 bottom
RX37  0_0201_5%  [R_0201]  106.05 30.53 180 bottom
RX38  10K_0402_5%  [R_0402]  99.72 39.87 0 bottom
RX39  10K_0402_5%  [R_0402]  101.7 31.69 270 bottom
SW1  S TACT SW TST71A-N-220-S017 SPST H0  [SW_TST71-N-220-T170-S017_2P]  32.66 63.69 0 top
SW2  S TACT SW TST71A-N-220-S017 SPST H0  [SW_TST71-N-220-T170-S017_2P]  28.61 61.51 90 bottom
T2  -  [TPC12]  127.73 85.15 0 top
T3  -  [TPC12]  130.97 85.59 0 top
T4  -  [TPC12]  132.3 84.45 0 top
T5  -  [TPC12]  127.22 58.92 0 top
T6  -  [TPC12]  127.22 60.57 0 top
T7  -  [TPC12]  129.19 85.78 0 top
T8  -  [TPC12]  124.68 92.76 270 top
T9  -  [TPC12]  123.35 92.71 270 top
T10  -  [TPC12]  123.8 84.96 0 top
T11  -  [TPC12]  122.59 85.85 0 top
T12  -  [TPC12]  119.22 74.96 0 top
T13  -  [TPC12]  129.42 58.9 0 top
T14  -  [TPC12]  120.47 65.38 0 top
T15  -  [TPC12]  121.23 64.31 0 top
T16  -  [TPC12]  124.05 82.42 0 top
T17  -  [TPC12]  150.5 90.03 180 bottom
T18  -  [TPC12]  125.13 81.72 0 top
T43  PAD  [TPC12]  19.35 87.12 0 top
T44  PAD  [TPC12]  20.29 84.7 0 top
T46  -  [TPC12]  196.25 66.86 0 top
T47  -  [TPC12]  119.79 127.87 0 top
T48  -  [TPC12]  118.56 127.44 0 top
T49  -  [TPC12]  118.51 125.94 0 top
T50  -  [TPC12]  125.51 127.43 0 top
T51  -  [TPC12]  126.8 127.29 0 top
T52  -  [TPC12]  117.1 127.14 0 top
T53  -  [TPC12]  120.8 127.96 0 top
T54  -  [TPC12]  116.87 125.85 0 top
T55  -  [TPC12]  116.79 128.39 0 top
T56  -  [TPC12]  118.27 124.61 0 top
T57  -  [TPC12]  118.77 123.03 0 top
T58  -  [TPC12]  119.64 126.58 0 top
T59  -  [TPC12]  119.49 125.09 0 top
T60  -  [TPC12]  116.88 120.38 180 bottom
T61  -  [TPC12]  118.34 120.32 180 bottom
T62  -  [TPC12]  122.1 125.12 0 top
T63  -  [TPC12]  120.79 125.18 0 top
T64  -  [TPC12]  121 120.49 180 bottom
T65  -  [TPC12]  119.73 120.41 180 bottom
T66  -  [TPC12]  123.86 120.53 180 bottom
T67  -  [TPC12]  122.93 119.63 180 bottom
T68  -  [TPC12]  110.85 126.06 180 bottom
T69  -  [TPC12]  118.91 132.83 0 top
T100  -  [TPC12]  224.18 59.33 0 top
T101  -  [TPC12]  125.03 49.46 180 bottom
T102  -  [TPC12]  124.93 51.19 180 bottom
T103  -  [TPC12]  127.81 51.16 0 top
T104  -  [TPC12]  129.85 53.26 0 top
T105  -  [TPC12]  129.96 51.49 180 bottom
T106  -  [TPC12]  125.38 50.8 0 top
T107  -  [TPC12]  126.53 51.37 0 top
T108  -  [TPC12]  129.38 49.84 0 top
T109  -  [TPC12]  129.26 51.43 0 top
T111  -  [TPC12]  127.24 51.09 180 bottom
T112  -  [TPC12]  133.13 53.72 0 top
T113  -  [TPC12]  124.58 44.76 180 bottom
T114  -  [TPC12]  106.35 38.91 180 bottom
T115  -  [TPC12]  127.87 57.73 0 top
T116  -  [TPC12]  102.76 31.86 180 bottom
T117  -  [TPC12]  124.84 52.37 0 top
T118  -  [TPC12]  123.31 48.09 180 bottom
T119  -  [TPC12]  124.71 48.05 180 bottom
T120  -  [TPC12]  224.16 60.63 0 top
T121  -  [TPC12]  224.2 62.05 0 top
T122  -  [TPC12]  224.51 63.43 0 top
T123  -  [TPC12]  222.59 57.84 0 top
T124  -  [TPC12]  223.94 57.78 0 top
T125  -  [TPC12]  225.84 67.56 0 top
TL1  350UH_NS0013LF  [BOTH_NS0013LF_16P]  16.98 64.24 90 bottom
TL2  350UH_NS0013LF  [BOTH_NS0013LF_16P]  16.98 73.13 270 top
TP1  PAD  [TPC12]  44.28 125.92 0 top
TP2  PAD  [TPC12]  40.93 125.81 0 top
TP3  PAD  [TPC12]  39.67 113.9 0 top
U2  -  [SY6288C20AAC_SOT23-5]  221.65 45.26 180 top
U3  EM5209VF DFN 14P DUAL LOAD SW  [TPS22966DPUR_SON14_2X3]  123.87 115.3 270 bottom
U4  EM5209VF DFN 14P DUAL LOAD SW  [TPS22966DPUR_SON14_2X3]  40.03 98.67 270 top
U5  -  [SY6288D20AAC_SOT23-5]  211.81 34.98 270 top
U6  EM5209VF DFN 14P DUAL LOAD SW  [TPS22966DPUR_SON14_2X3-S]  36.6 51.68 270 top
U7  -  [DMN3009LFV-13_POWERDI3333-8-5]  152.56 41.12 180 top
U8  G781-1P8F MSOP 8P  [NCT7718W_MSOP8]  181.33 63.03 225 bottom
U58  FE1.1S-BSOP28BLTR SSOP 28P HUB CTRL  [FE1P1S-BSOP28BCTR_SSOP28]  219.72 51.81 90 top
UA1  ALC3234-CG_MQFN48_6X6  [ALC3246-CG_MQFN48_6X6-S]  30.33 11.07 180 top
UC1  FP5_BGA1140~D  [FP5_BGA_1140P]  136.53 86.61 180 bottom
UC2  NL17SZ07DFT2G_SC70-5  [SN74LVC1G07DCKR_SC70-5]  133.11 88.12 90 top
UC3  NL17SZ07DFT2G_SC70-5  [SN74LVC1G07DCKR_SC70-5]  44.18 60.68 180 top
UC4  MC74VHC1G08DFT2G SC70 5P  [NC7SZ08P5X_NL_SC70-5]  108.75 119.31 90 bottom
UC5  NL17SZ07DFT2G_SC70-5  [SN74LVC1G07DCKR_SC70-5]  130.8 95.07 270 top
UC7  W25Q128FWSIQ SOIC  [GD25LB128CSIGR_SO8]  129.89 40.19 270 bottom
UC8  AP2138N-1.5TRG1_SOT23-3  [AP2138N-1P5TRG1_SOT23-3]  155.57 28.51 90 top
UC9  MC74VHC1G08DFT2G SC70 5P  [NC7SZ08P5X_NL_SC70-5]  145 44.38 90 bottom
UC20  -  [SY6288C20AAC_SOT23-5]  133.78 25.48 180 bottom
UC21  MC74VHC1G08DFT2G SC70 5P  [NC7SZ08P5X_NL_SC70-5]  23.63 24.47 180 top
UE1  -  [KB9022QD_LQFP128_14X14]  37.35 67.78 90 top
UI1  -  [SY6288D20AAC_SOT23-5]  18.9 56.19 0 bottom
UL1  RTL8106E-CG_QFN32_4X4  [RTL8106E-CG_QFN32_4X4-S]  22.07 80.85 0 top
UL2  -  [SY6288C20AAC_SOT23-5]  32.16 88.01 90 top
US1  SN75LVCP601RTJR_QFN20_4X4  [PS8520BTQFN20GTR2_TQFN20_4X4-S]  182.73 34.65 270 top
US4  -  [LNG2DMTR_LGA12_2X2]  204.45 31.14 90 top
US5  -  [SY6288D20AAC_SOT23-5]  189.27 37.39 270 top
UT1  -  [CYPD4225-40LQXIT_QFN40_6X6]  39.44 125.55 180 bottom
UT3  -  [AP2330W-7_SC59-3]  32.36 110.61 90 top
UT4  -  [RT9069-33GB_SOT23-5]  27.91 115.34 0 top
UT8  SY6861A1AAC SOT23  [G518A1TO1U_TSOT23-5]  36.51 129.16 90 top
UT9  -  [TUSB544RNQ_QFN40_4X6]  18.16 125.71 270 bottom
UT10  -  [NX3DV221GM_XQFN10U10_2X1P55]  27.37 129.67 90 bottom
UU1  -  [SY6288D20AAC_SOT23-5]  195.29 34.72 180 top
UV1  2160856030-A0_FCBGA631  [216-0842024-A11-MAR_FCBGA_631P]  134.54 122.6 90 bottom
UV2  MC74VHC1G08DFT2G_SC70-5  [SN74AHC1G08DCKR_SC70-5]  109.4 122.6 180 bottom
UV8  MC74VHC1G08DFT2G_SC70-5  [SN74AHC1G08DCKR_SC70-5]  48.07 87.46 0 top
UV12  H5GC4H24AJR-R0C_BGA170  [H5GC4H24AJR-R0C_BGA_170P]  148.71 136.32 90 top
UV13  H5GC4H24AJR-R0C_BGA170  [H5GC4H24AJR-R0C_BGA_170P]  161.51 136.32 90 bottom
UV14  H5GC4H24AJR-R0C_BGA170  [H5GC4H24AJR-R0C_BGA_170P]  161.51 129.71 270 top
UV15  H5GC4H24AJR-R0C_BGA170  [H5GC4H24AJR-R0C_BGA_170P]  148.71 129.71 270 bottom
UW1  -  [SY6288C20AAC_SOT23-5]  71.13 137.79 90 top
UX1  NPCT650VB2YX QFN 32P 5X5  [NPCT650VB2YX_QFN32_5X5]  100.23 34.3 0 bottom
Y1  12MHZ_12PF_5YEA12000122IFA2Q3  [Y_5YEA12000122IFA2Q3_4P]  219.32 48.79 180 top
YC2  48MHZ_8PF_X3S048000D81H-W  [Y_X3S048000D81H-W_4P]  147.44 49.8 270 bottom
YC3  32.768KHZ_12.5PF_CM31532768DZFT  [Y_CM31532768DZFT_2P]  146.02 54.71 270 bottom
YL1  25MHZ_10PF_7V25000014  [Y_7V25000014_4P]  14.68 85.44 270 top
YV1  27MHZ_10PF_7V27000050  [Y_7V27000011_4P]  108.36 145.16 270 bottom
ZTB01  PAD  [TPC12]  210.12 47.11 0 top
ZTB02  PAD  [TPC12]  206.31 49.58 0 top
ZTB03  PAD  [TPC12]  209.03 44.46 0 top

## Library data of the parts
C1 C15 C16 C18 C20-C22 C24-C28 C31-C34 C38 C41-C44 C47 C52 C54 C56-C58 C61 C65 C66 C300-C305 C310 C636 C796 C797 C4311-C4314 C4321 C4322 CA2 CA4 CA7 CA10 CA14 CA17 CA26-CA31 CA39-CA42 CA46-CA52 CA55 CA57 CA66-CA68 CC1-CC8 CC10-CC14 CC30-CC39 CC61 CC62 CC67 CC68 CC70 CC71 CC73 CC74 CC76-CC78 CC81-CC91 CC94 CC95 CC100 CC250 CC251 CC615 CC635 CC682 CC686 CC1189 CC1190 CC1192 CD19-CD28 CD30-CD32 CD36 CD38-CD40 CD47-CD55 CD58-CD61 CD64 CD67 CD68 CE2-CE9 CE11-CE14 CE16-CE19 CH2-CH4 CI1-CI10 CL6 CL11 CL12 CL15 CL18-CL23 CS1-CS11 CS13-CS20 CS22-CS25 CS29 CS32 CS33 CS40 CS44-CS51 CT4 CT6 CT7 CT9-CT13 CT26-CT29 CT32-CT47 CT54 CT55 CT58-CT62 CU4 CU6-CU10 CU14-CU16 CU18-CU20 CU37-CU41 CV1 CV25 CV33 CV52 CV57 CV59 CV62 CV63 CV71-CV80 CV82 CV85-CV87 CV89 CV90 CV92-CV121 CV123-CV127 CV153 CV155 CV157 CV158 CV160-CV162 CV164-CV166 CV169 CV170 CV173-CV181 CV198 CV210 CV211 CV213 CV216 CV219 CV221 CV227 CV230 CV233 CV235 CV242 CV243 CV247 CV248 CV304-CV309 CV312 CV313 CV333-CV336 CV341-CV344 CV390 CV391 CV394 CV395 CW5-CW7 CW9-CW11 CW13-CW16 CX2 CX3 CX8-CX13 EC1 EC2 PC7 PC9-PC18 PC21-PC23 PC315 PC316 PC501 PC502 PC505-PC508 PC515-PC518 PC1805-PC1810 PC2503-PC2505 PCA01 PCA02 PCA05 PCA06 PCA07 PCB01 PCB02 PCB18-PCB24 PCB26 PCB28 PCB29 PCB33-PCB35 PCB38-PCB47 PCF03 PCF04 PCF05 PCH01 PCH02 PCH09-PCH12 PCH14-PCH20 PCM01 PCM02 PCM11 PCM12 PCM15-PCM19 PCM22-PCM24 PCS01 PCS02 PCS03 PCS04 PCS05 PCS06 PCS07 PCS08 PCS10-PCS14 PCS16 PCS17 PCS19 PCS20 PCS61 PCS62 PCV04 PCV05 PCV06 PCV07 PCV08 PCV10 PCV16-PCV23 PCV25-PCV29 PCV31 PCV33 PCV34 PCV37 PCW01 PCW02 PCW09-PCW12 PCW14-PCW17 PCZ01 PCZ02 PCZ03 PCZ04 PCZ05 PCZ06 PCZ09 PCZ11 PCZ16-PCZ18 PCZ20 PCZ21 PCZ24 PCZ25 PCZ27-PCZ33 PCZ35 PCZ39 PCZ40 PCZ42 PCZ45 PCZ47-PCZ49 = C_0402
C5 C12-C14 C19 C23 C30 C35 C39 C40 C45 C46 C48-C51 C53 C55 C60 CA1 CA3 CA6 CA9 CA12 CA16 CA19-CA21 CA37 CA38 CA53 CA54 CA56 CC15 CC16 CC21-CC25 CC28 CC29 CC40-CC56 CC59 CC60 CC63-CC66 CC69 CC72 CC75 CC79 CC80 CC92 CC93 CC1191 CC1193 CD34 CD37 CD41-CD46 CD56 CD57 CD65 CD66 CE1 CL24 CL25 CS70 CS71 CT3 CT5 CT8 CT17 CT21 CT50 CT53 CT56 CU3 CU13 CV68 CV70 CV81 CV84 CV88 CV91 CV122 CV225 CV238 CW8 CW12 PC5 PC6 PC8 PC509 PC1801-PC1804 PCA08 PCA101-PCA110 PCB25 PCB27 PCB30 PCB36 PCB37 PCF01 PCF02 PCF06 PCH05 PCH06 PCH07 PCH08 PCH13 PCM05 PCM06 PCM07 PCM08 PCM09 PCM10 PCM13 PCM14 PCM20 PCM21 PCS09 PCS15 PCS63 PCV09 PCV11 PCV12 PCV24 PCV30 PCV32 PCW05 PCW06 PCW07 PCW08 PCW13 PCZ07 PCZ08 PCZ22 PCZ23 PCZ26 PCZ34 PCZ46 PCZ50 PCZ101-PCZ120 = C_0603
C29 CF1 CS12 CS21 CS26 CS31 CS72 CS73 CT22 CT49 CT57 CU1 CU2 CU5 CU11 CU12 CU17 PC312-PC314 PC503 PC504 PC510-PC514 PC519 PC2501 PC2502 PCA03 PCA04 PCB03 PCB04 PCB05 PCB06 PCB10-PCB17 PCB31 PCB32 PCH03 PCH04 PCM03 PCM04 PCV01 PCV02 PCV03 PCV13-PCV15 PCV35 PCV36 PCW03 PCW04 PCZ13-PCZ15 PCZ19 PCZ38 PCZ41 PCZ43 PCZ44 = C_0805
CA23 CA24 = C_0603: room: AUDIO
CA25 = C_0402: room: AUDIO
CC9 = C_0402: room: CPU
CC26 CC27 CC57 CC58 = C_0603: room: CPU
CD1 CD8-CD16 CD29 = C_0402: room: DDR4
CD2-CD7 CD17 CD18 = C_0603: room: DDR4
CD35 PCA171 PCA172 PCV171 PCV172 PCZ171-PCZ174 = C_D2
CL3-CL5 CL7-CL9 = C_0402: room: LAN
CL10 = C_1206
CLIP2 = EMIST_SQ-55G_1P
CLRP1 = SHORTPADS: User Part Number: PART#
CV2-CV8 CV11 CV15 CV17 CV18 CV20 CV21 CV26 CV28 CV29 CV34 CV35 CV39-CV42 CV46-CV51 CV53 CV56 CV58 CV60 CV64-CV66 = C_0402: room: GPU
CV19 CV27 CV30 CV38 CV43-CV45 CV54 CV55 CV61 CV67 CV69 = C_0603: room: GPU
D1 D5 D6 DX1 = RB751V-40_SOD323-2
D2 = L30ESD24VC3-2_SOT23-3
DA1 DA2 DA6 ED2 = L03ESDL5V0CC3-2_SOT23-3
DA3 = BAT54C-7-F_SOT23-3
DA5 = AZ5123-02SPR7G_SOT23-3
DC1 = BAS40C_SOT23-3
DF1 DH1 DH2 = DB2J31400L_SOD323-2
DT1 DT2 = RB551V-30_SOD323-2
DT3-DT10 = ESD101-B1-02ELS_TSSLP-2-4-2
DU2 DX3 EU2 EU4 = AZC199-02SPR7G_SOT23-3
EU3 EU5 EU7 EU8 = L05ESDL5V0NA-4_SLP2510P8-10-9
EU4012 PD1 PD5 PD6 = TVNST52302AB0_SOT523-3
F1 F2 = F_SMD1812P110TF-24
F3 = F_MF-NSMF050-2
FD1-FD4 = FIDUCIAL_C40M80: room: ETY-ROOM
FI1 = F_1206L150PR
H1 = H_3P0: room: SCREW
H3 = H_5P0-G: room: SCREW
H4-H7 = H_3P0-G: room: SCREW
H8 = H_3P3
H9 H10 = H_3P5
H11 H12 = H_3P2
H13 = H_3P0X4P0
H14 = H_5P6N
HCPU1 = H_4P0X3P7
HCPU2 = H_3P7
HCPU3 = H_4P0
HCPU4 = H_3P7X4P0
J1 J4 PJP302 PJPH02 PJPM02 PJPS01 PJPW02 = JUMP_43X118
J3 J5 JP4 JP5 JP10 PJP502 PJP503 PJP1802 PJPA01 = JUMP_43X79
JCCG4_T = DC021611210
JCRT = ACES_51625-01601-001_16P-T
JDIMM1 = LOTES_ADDR0206-P001A02_260P: room: DDR4
JDIMM2 = LOTES_ADDR0205-P001A02_260P: room: DDR4
JEDP1 = ACES_51540-04001-P01_40P
JFAN1 JSPK1 = ACES_50224-00401-001_4P
JFP = ACES_51522-00601-001_6P-NPM
JFP1 = ACES_51522-00801-001_8P
JH1 = ACES_91960-0084L_8P-T-NPM
JHDD1 = ACES_51625-01201-001_12P
JHDMI1 = ACON_HMRF6-AK120C_19P-T
JHP1 = YUQIU_PJ753-F07J1BE-B_7P-T
JIOB1 = ACES_51524-0160N-001_16P
JKB1 = ACES_50699-03041-P01_30P
JKBBL1 = ACES_51575-00401-001_4P-T
JODD1 = ACES_50673-0120N-001_12P-T
JP2 JP3 PJP1801 PJP2501 PJP2502 PJPF01 PJPF02 PJPM03 = JUMP_43X39
JPWR1 = JXT_FP226H-004S1AM_4P
JRJ45 = SINGA_2RJ3076-078211F_8P-T
JSSD1 = LCN_DAN05-67306-0103_75P
JTP1 = ACES_51524-0080N-001_8P
JUSB1 JUSB2 = ACON_TARAN-9R1391_9P
JUSBC1 = JAE_DX07S024JJ2R1300_24P
JWLAN1 = LCN_DAN05-67306-0100_75P
L1 LT1 LT3 LU3 LU6-LU8 = INPAQ_MCM1012B900F06BP_4P
LA1-LA4 LV2 LV4 LV7 LV8 PH1 PHA01 PHA02 PHV01 PHV02 PHZ01 PHZ02 PR1 PR2 PR7-PR17 PR21 PR22 PR31 PR33-PR53 PR60-PR66 PR100 PR302-PR304 PR306-PR308 PR504 PR506 PR508-PR511 PR1802 PR1803 PR1805 PR1807 PR2502-PR2504 PRA04 PRB02 PRB03 PRB05 PRB07 PRB09 PRB11 PRB13 PRB19 PRB20 PRB22-PRB27 PRB29-PRB33 PRB36-PRB44 PRF01 PRF02 PRF03 PRF04 PRH02 PRH03 PRH04 PRH05 PRH08 PRH09-PRH19 PRM03 PRM06 PRM07 PRM10-PRM13 PRS01 PRS02 PRS03 PRS04 PRS05 PRS06 PRS07 PRS08 PRS09-PRS16 PRS18 PRS23 PRS25-PRS30 PRS32-PRS45 PRS61-PRS66 PRV02 PRV03 PRV04 PRV05 PRV08 PRV09 PRV10 PRV12 PRV14-PRV19 PRV22 PRV25-PRV33 PRV35 PRW01 PRW02 PRW03 PRW04 PRW05 PRW09-PRW12 PRZ01 PRZ02 PRZ03 PRZ04 PRZ05 PRZ07 PRZ08 PRZ09-PRZ15 PRZ20 PRZ22 PRZ24-PRZ26 PRZ28-PRZ37 PRZ39 PRZ42 PRZ43 PRZ46 PRZ47 R6 R10-R15 R17-R20 R23 R27 R28 R30-R34 R36 R58 R59 R61 R63-R65 R68 R69 R82 R83 R300 R438 R702-R705 R800 RA7 RA8 RA19 RA22-RA28 RA31 RA32 RA41 RA43-RA45 RA49 RA54-RA56 RA58 RC1-RC3 RC8 RC10 RC13 RC15 RC16 RC24 RC26 RC28 RC29 RC33 RC34 RC36 RC40-RC42 RC49 RC51 RC62 RC94 RC97-RC99 RC102-RC104 RC449 RC602 RC615-RC622 RC630 RC631 RC639 RC640 RC642 RC646 RC661 RC663 RC664 RC680 RC681 RC700 RC701 RC703 RC704 RC711 RC712 RC801 RC902 RC905 RC906 RC914 RC938 RC939 RC1689 RC1695-RC1697 RC1706 RC1707 RC6121-RC6127 RC6130 RE2-RE5 RE8 RE9 RE11 RE12 RE14 RE17-RE19 RE23-RE25 RE31 RE37 RE39-RE42 RE44 RE506 RE507 RE509 RE510 RF1-RF3 RH21-RH28 RI2 RI6 RI9 RI13 RI15-RI17 RI20-RI28 RL2 RL6 RL10 RL12 RL14-RL17 RP1-RP3 RP5 RS3-RS13 RS15-RS29 RS60-RS63 RT1-RT4 RT6 RT17-RT32 RT34-RT37 RT40-RT55 RT60-RT65 RT70-RT73 RT101 RT112 RT113 RT115-RT119 RT130-RT134 RV1-RV3 RV8 RV11 RV13 RV15-RV17 RV24 RV28 RV29 RV32-RV39 RV53-RV55 RV59 RV71 RV79 RV85-RV89 RV116-RV121 RV123 RV131-RV135 RV150-RV159 RV162-RV165 RV260 RV368 RV369 RW6-RW8 RW10-RW15 RX7-RX9 RX13-RX16 RX25 RX38 RX39 = R_0402
LA6 LA9 = MURAT_BLM15PX330SN1D_2P
LA7 LA8 PR502 PR503 PR507 PR1801 PR2501 PRB10 PRB14 PRB16 PRB21 PRB28 PRB34 PRB35 PRH01 PRM08 PRM09 PRV20 PRV34 PRV36 PRZ06 PRZ16 PRZ19 PRZ38 PRZ40 R3 R4 R21 R24 R26 RA2 RA53 RC39 RC6128 RC6129 RE30 RE35 RE36 RE43 RE50 RE52 = R0402_0OHM
LA10 LV6 = MURAT_BLM15BB221SN1D_2P
LE1 LE2 = KC_FBMA-L11-160808-800LMT_2P
LED1 = LED_LTW-295DSKS-5A_4P
LI1-LI4 LU1 LU2 LU4 LU5 LU13-LU16 = INPAQ_HCM1012GH900BP_4P
LV3 RV4-RV6 RV9 RV12 RV21 RV40 RV41 RV48-RV52 RV80-RV84 = R_0402: room: GPU
LX1 = TAI-T_HCB2012KF-221T30_2P
PBATT1 = ACES_50458-01001-P01_10P-T
PC1-PC4 = C_0402: room: DCIN
PC301 = C_0402: room: ETY-ROOM
PC302 PC305-PC308 = C_0402: room: 3_5V
PC303 PC304 = C_0805: room: 3_5V
PC309 = C_0603: room: 3_5V
PC310 PC311 = C_0805: room: ETY-ROOM
PCB07 PCZ36 PCZ37 = C_EEFCX1E330R-NPM
PCB08 = C_6P3X4P5
PCZ10 PCZ12 = C_25CL33LD
PD2 PD3 = BAV99W_SC70-3
PD4 PDS02 = PDS5100H-13_POWERDI5-3
PD10 PD11 PDS03 = LRB715FT1G_SOT323-3
PD12 = DFLS160-7_POWERDI123-2
PD501 PDB01 PDB02 PDB03 PDB05 PDS04 PDS05 PDS06 = SDMK0340L-7-F_SOD323-2
PDB04 PDS01 = BAT54CW_SOT323-3
PJP1-PJP3 PJP501 PJPV01 PJPZ01 = JUMP_43X79-NPM
PJP301 PJPH01 PJPM01 PJPW01 = JUMP_43X39-NPM
PJPB01 = JUMP_43X118-NPM
PJPDC1 = ACES_50458-00601-001_6P-T
PL1 PL2 = 5A_Z150_1210_2P: room: DCIN
PL3 = MURAT_BLM15AG102SN1D_2P
PL4 = 5A_Z150_1210_2P: room: BATT
PL301 PL501 PLH01 PLM01 = L_7X7X3_M_2P
PL311 PL1811 PLH11 PLM11 PLS11 PLS12 PLW11 = TAI-T_HCB2012KF-121T50_2P
PL511 PLB11 PLV11 PLZ01 = 5A_Z150_1210_2P
PL1801 PLW01 = L_5X5X3_M_2P
PLA01 PLV01 PLV02 PLZ02 PLZ03 = L_7X7X4_M
PLB01 = CYNTE_PCMB104T-1R0MH_2P
PQ1 = FDV301N-G_SOT23-3
PQ2 = MMST3904-7-F_SOT323-3
PQ3 PQ4 PQB03 PQS01 PQS02 PQS61 = AON7409_DFN8-5
PQ5 PQ6 PQ11 PQ15-PQ18 PQ20 PQB04 PQH01 PQS04 PQS07 PQS08 PQS11 PQS12 PQS14 PQS62 PQS64 = DMN65D8LW-7_SOT323-3
PQ12 PQ13 PQH02 PQS03 PQS05 PQS10 PQS30 = DMN65D8LDW-7_SOT363-6
PQ19 PQS06 PQS13 PQS63 = AO3409_SOT23-3
PQA01 PQZ01 PQZ02 PQZ03 PQZ04 = AON6970_DFN5X6D-8-7
PQB01 PQB02 PQV01 PQV02 PQV03 PQV04 = AON6994_DFN5X6D-8-7
PQM01 = AON7934_DFN3X3A8-10
PR3 PR5 PR6 = R_0402: room: BATT
PR4 = R_0402: room: ETY-ROOM
PR32 PR305 PR505 PR1804 PRA02 PRB17 PRB18 PRH07 PRM01 PRV06 PRV23 PRW07 PRZ23 PRZ44 RM1 RT33 = R_1206
PR301 PR501 PRV01 PRV21 RA52 RV27 RV30 RV31 RV364 RW2-RW4 = R0603_0OHM
PRA01 PRA03 PRB04 PRB06 PRB15 PRH06 PRM02 PRM04 PRM05 PRV07 PRV13 PRV24 PRW06 PRZ17 PRZ21 PRZ27 PRZ41 PRZ45 R9 R16 R56 R700 R701 R801 RA57 RC1672 RC1700 RE6 RE508 RL3 RL7 RL9 RL18-RL20 RX26 RX27 = R_0603
PRB01 PRB12 = R_1206_4P-D
PRB08 R5 RE1 = R_0805
PU1 UT4 = RT9069-33GB_SOT23-5
PU2 PUB02 PUS02 UV2 UV8 = SN74AHC1G08DCKR_SC70-5
PU301 = SY8286BRAC_QFN20_3X3
PU501 = SY8288CRAC_QFN20_3X3
PU1801 = RT8061AZQW_WDFN10_3X3
PU2501 PUF01 = RT9059GSP_SO8
PUB01 = ISL9538HRTZ-T_TQFN32_4X4
PUH01 PUW01 = RT6226AGQUF_UQFN12_3X3
PUM01 = RT8207PGQW_WQFN20_3X3
PUS01 = LM393DGKR_VSSOP8
PUS03 = TC7SH32FU_SSOP5
PUS04 = AP2204R-5P0TRG1_SOT89-3
PUV01 PUZ01 = ISL62771HRTZ-T_TQFN40_5X5-S
Q1 Q3 Q5 QA1 QT4 QT5 = LN2306LT1G_SOT23-3
Q2 Q4 Q6 Q7 Q9 Q15 Q16 QC27 QI1 QT3 = 2N7002K_SOT23-3
Q10 = LMBT3904LT1G_SOT23-3
Q11 Q14 Q26 QI3 QS1 = DMN66D0LDW-7_SOT363-6
Q17 = 2N7002KW_SOT323-3
QC1 = MESS138W-G_SOT323-3
QC3 QT6 QV1 = 2N7002KDWH_SOT363-6
QE1 = 2N7002BKW_SOT323-3
QI2 = MMBT3904_NL_SOT23-3
QW1 = SSM3K7002FU_SC70-3
R7 R8 RI1 RI3 RI4 RI7 RI8 RI10 RI12 RI14 RT9 RT10 RT102-RT111 RU1-RU16 = R_0402-NPM
RA10 RA12-RA14 RA29 = R_0402: room: AUDIO
RA30 = R0402_0OHM: room: AUDIO
RA38 RA51 = R0805_0OHM
RC4-RC7 RC12 RC17-RC20 RC22 RC25 RC27 RC30 RC44 RC46-RC48 RC52-RC54 RC56-RC61 RC74 RC95 = R_0402: room: CPU
RC96 = R0402_0OHM: room: CPU
RD1-RD4 = R_0402: room: DDR4
RL1 RL4 RL5 RL8 = R_0402: room: LAN
RP4 RPC1 RPC3-RPC5 RPC30 RPC64 RPH1 RPI3 RPV34 = RP_0804_8P4R
RX1-RX6 RX28-RX37 = R_0201
SW1 SW2 = SW_TST71-N-220-T170-S017_2P
T2-T18 T43 T44 T46-T69 T100-T109 T111-T125 TP1-TP3 ZTB01 ZTB02 ZTB03 = TPC12
TL1 TL2 = BOTH_NS0013LF_16P
U2 UC20 UL2 UW1 = SY6288C20AAC_SOT23-5
U3 U4 = TPS22966DPUR_SON14_2X3
U5 UI1 US5 UU1 = SY6288D20AAC_SOT23-5
U6 = TPS22966DPUR_SON14_2X3-S
U7 = DMN3009LFV-13_POWERDI3333-8-5
U8 = NCT7718W_MSOP8
U58 = FE1P1S-BSOP28BCTR_SSOP28
UA1 = ALC3246-CG_MQFN48_6X6-S: room: AUDIO
UC1 = FP5_BGA_1140P: room: CPU
UC2 = SN74LVC1G07DCKR_SC70-5: room: CPU
UC3 UC5 = SN74LVC1G07DCKR_SC70-5
UC4 UC9 UC21 = NC7SZ08P5X_NL_SC70-5
UC7 = GD25LB128CSIGR_SO8
UC8 = AP2138N-1P5TRG1_SOT23-3
UE1 = KB9022QD_LQFP128_14X14
UL1 = RTL8106E-CG_QFN32_4X4-S: room: LAN
US1 = PS8520BTQFN20GTR2_TQFN20_4X4-S
US4 = LNG2DMTR_LGA12_2X2
UT1 = CYPD4225-40LQXIT_QFN40_6X6
UT3 = AP2330W-7_SC59-3
UT8 = G518A1TO1U_TSOT23-5
UT9 = TUSB544RNQ_QFN40_4X6
UT10 = NX3DV221GM_XQFN10U10_2X1P55
UV1 = 216-0842024-A11-MAR_FCBGA_631P: room: GPU
UV12-UV15 = H5GC4H24AJR-R0C_BGA_170P
UX1 = NPCT650VB2YX_QFN32_5X5
Y1 = Y_5YEA12000122IFA2Q3_4P
YC2 = Y_X3S048000D81H-W_4P: room: CPU
YC3 = Y_CM31532768DZFT_2P
YL1 = Y_7V25000014_4P: room: LAN
YV1 = Y_7V27000011_4P: room: GPU

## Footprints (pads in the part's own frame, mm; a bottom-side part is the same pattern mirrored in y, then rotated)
2N7002BKW_SOT323-3
  oval 0.61x0.559 smd: 1(0,0) 2(-0.65,-1.85) 3(0.65,-1.85)
2N7002K_SOT23-3
  oval 1.016x1.524 smd: 1(0,0) 2(0.965,2.083) 3(-0.965,2.083)
2N7002KDWH_SOT363-6
  oval 0.356x0.889 smd: 1(0,0) 2(0.65,0) 3(1.3,0) 4(1.3,1.6) 5(0.65,1.6) 6(0,1.6)
2N7002KW_SOT323-3
  oval 0.66x0.864 smd: 1(0,0) 2(0.65,1.85) 3(-0.65,1.85)
5A_Z150_1210_2P
  rect 0.991x2.997 smd: 1(0,0) 2(2.7,0)
216-0842024-A11-MAR_FCBGA_631P
  round 0.406 smd: A3(0.8,0) A30(20.8,0) A32(21.6,0) AB7(3.2,-15) AB8(4,-15) AB9(4.8,-15) AB10(5.6,-15) AB23(16,-15) AB24(16.8,-15) AB25(17.6,-15) AB26(18.4,-15) AC11(6.6,-16) AC13(7.8,-16) AC14(9,-16) AC16(10.2,-16) AC17(11.4,-16) AC19(12.6,-16) AC20(13.8,-16) AC22(15,-16) AD11(6.6,-16.8) AD13(7.8,-16.8) AD14(9,-16.8) AD16(10.2,-16.8) AD17(11.4,-16.8) AD19(12.6,-16.8) AD20(13.8,-16.8) AD22(15,-16.8) AE11(6.6,-17.6) AE13(7.8,-17.6) AE14(9,-17.6) AE16(10.2,-17.6) AE17(11.4,-17.6) AE19(12.6,-17.6) AE20(13.8,-17.6) AE22(15,-17.6) AF11(6.6,-18.4) AF13(7.8,-18.4) AF14(9,-18.4) AF16(10.2,-18.4) AF17(11.4,-18.4) AF19(12.6,-18.4) AF20(13.8,-18.4) AF22(15,-18.4) AK1(0,-20.8) AK3(0.8,-20.8) AK30(20.8,-20.8) AK32(21.6,-20.8) AM1(0,-21.6) AM3(0.8,-21.6) AM30(20.8,-21.6) AM32(21.6,-21.6) C1(0,-0.8) C3(0.8,-0.8) C30(20.8,-0.8) C32(21.6,-0.8) G11(6.6,-3.2) G13(7.8,-3.2) G14(9,-3.2) G16(10.2,-3.2) G17(11.4,-3.2) G19(12.6,-3.2) G20(13.8,-3.2) G22(15,-3.2) H11(6.6,-4) H13(7.8,-4) H14(9,-4) H16(10.2,-4) H17(11.4,-4) H19(12.6,-4) H20(13.8,-4) H22(15,-4) J11(6.6,-4.8) J13(7.8,-4.8) J14(9,-4.8) J16(10.2,-4.8) J17(11.4,-4.8) J19(12.6,-4.8) J20(13.8,-4.8) J22(15,-4.8) K11(6.6,-5.6) K13(7.8,-5.6) K14(9,-5.6) K16(10.2,-5.6) K17(11.4,-5.6) K19(12.6,-5.6) K20(13.8,-5.6) K22(15,-5.6) L7(3.2,-6.6) L8(4,-6.6) L9(4.8,-6.6) L10(5.6,-6.6) L23(16,-6.6) L24(16.8,-6.6) L25(17.6,-6.6) L26(18.4,-6.6) N7(3.2,-7.8) N8(4,-7.8) N9(4.8,-7.8) N10(5.6,-7.8) N23(16,-7.8) N24(16.8,-7.8) N25(17.6,-7.8) N26(18.4,-7.8) P7(3.2,-9) P8(4,-9) P9(4.8,-9) P10(5.6,-9) P23(16,-9) P24(16.8,-9) P25(17.6,-9) P26(18.4,-9) T7(3.2,-10.2) T8(4,-10.2) T9(4.8,-10.2) T10(5.6,-10.2) T23(16,-10.2) T24(16.8,-10.2) T25(17.6,-10.2) T26(18.4,-10.2) U7(3.2,-11.4) U8(4,-11.4) U9(4.8,-11.4) U10(5.6,-11.4) U23(16,-11.4) U24(16.8,-11.4) U25(17.6,-11.4) U26(18.4,-11.4) W7(3.2,-12.6) W8(4,-12.6) W9(4.8,-12.6) W10(5.6,-12.6) W23(16,-12.6) W24(16.8,-12.6) W25(17.6,-12.6) W26(18.4,-12.6) Y7(3.2,-13.8) Y8(4,-13.8) Y9(4.8,-13.8) Y10(5.6,-13.8) Y23(16,-13.8) Y24(16.8,-13.8) Y25(17.6,-13.8) Y26(18.4,-13.8)
  round 0.305 smd: A5(1.6,0) A7(3.2,0) A9(4.8,0) A11(6.4,0) A13(8,0) A15(9.6,0) A17(11.2,0) A19(12.8,0) A21(14.4,0) A23(16,0) A25(17.6,0) A27(19.2,0) A28(20,0) AA1(0,-14.4) AA3(0.8,-14.4) AA5(1.6,-14.4) AA6(2.4,-14.4) AA27(19.2,-14.4) AA29(20.4,-14.4) AA31(21.2,-14.4) AB2(0.4,-15.2) AB4(1.2,-15.2) AB6(2.4,-15.2) AB27(19.2,-15.2) AB28(20,-15.2) AB30(20.8,-15.2) AB32(21.6,-15.2) AC1(0,-16) AC3(0.8,-16) AC5(1.6,-16) AC6(2.4,-16) AC7(3.2,-16) AC8(4,-16) AC9(4.8,-16) AC10(5.6,-16) AC23(16,-16) AC24(16.8,-16) AC25(17.6,-16) AC26(18.4,-16) AC27(19.2,-16) AC29(20.4,-16) AC31(21.2,-16) AD2(0.4,-16.8) AD4(1.2,-16.8) AD6(2.4,-16.8) AD7(3.2,-16.8) AD8(4,-16.8) AD9(4.8,-16.8) AD10(5.6,-16.8) AD23(16,-16.8) AD24(16.8,-16.8) AD25(17.6,-16.8) AD26(18.4,-16.8) AD27(19.2,-16.8) AD28(20,-16.8) AD30(20.8,-16.8) AD32(21.6,-16.8) AE1(0,-17.6) AE3(0.8,-17.6) AE5(1.6,-17.6) AE6(2.4,-17.6) AE7(3.2,-17.6) AE8(4,-17.6) AE9(4.8,-17.6) AE10(5.6,-17.6) AE23(16,-17.6) AE24(16.8,-17.6) AE25(17.6,-17.6) AE26(18.4,-17.6) AE27(19.2,-17.6) AE29(20.4,-17.6) AE31(21.2,-17.6) AF2(0.4,-18.4) AF4(1.2,-18.4) AF6(2.4,-18.4) AF7(3.2,-18.4) AF8(4,-18.4) AF9(4.8,-18.4) AF10(5.6,-18.4) AF23(16,-18.4) AF24(16.8,-18.4) AF25(17.6,-18.4) AF26(18.4,-18.4) AF27(19.2,-18.4) AF28(20,-18.4) AF30(20.8,-18.4) AF32(21.6,-18.4) AG1(0,-19.2) AG3(0.8,-19.2) AG5(1.6,-19.2) AG6(2.4,-19.2) AG7(3.2,-19.2) AG8(4,-19.2) AG9(4.8,-19.2) AG10(5.6,-19.2) AG11(6.4,-19.2) AG12(7.2,-19.2) AG13(8,-19.2) AG14(8.8,-19.2) AG15(9.6,-19.2) AG16(10.4,-19.2) AG17(11.2,-19.2) AG18(12,-19.2) AG19(12.8,-19.2) AG20(13.6,-19.2) AG21(14.4,-19.2) AG22(15.2,-19.2) AG23(16,-19.2) AG24(16.8,-19.2) AG25(17.6,-19.2) AG26(18.4,-19.2) AG27(19.2,-19.2) AG29(20.4,-19.2) AG31(21.2,-19.2) AH1(0,-20) AH3(0.8,-20) AH5(1.6,-20) AH6(2.4,-20) AH8(4,-20) AH10(5.6,-20) AH12(7.2,-20) AH14(8.8,-20) AH16(10.4,-20) AH18(12,-20) AH20(13.6,-20) AH22(15.2,-20) AH24(16.8,-20) AH26(18.4,-20) AH28(20,-20) AH30(20.8,-20) AH32(21.6,-20) AJ7(3.2,-20.4) AJ9(4.8,-20.4) AJ11(6.4,-20.4) AJ13(8,-20.4) AJ15(9.6,-20.4) AJ17(11.2,-20.4) AJ19(12.8,-20.4) AJ21(14.4,-20.4) AJ23(16,-20.4) AJ25(17.6,-20.4) AJ27(19.2,-20.4) AK5(1.6,-20.8) AK6(2.4,-20.8) AK8(4,-20.8) AK10(5.6,-20.8) AK12(7.2,-20.8) AK14(8.8,-20.8) AK16(10.4,-20.8) AK18(12,-20.8) AK20(13.6,-20.8) AK22(15.2,-20.8) AK24(16.8,-20.8) AK26(18.4,-20.8) AK28(20,-20.8) AL7(3.2,-21.2) AL9(4.8,-21.2) AL11(6.4,-21.2) AL13(8,-21.2) AL15(9.6,-21.2) AL17(11.2,-21.2) AL19(12.8,-21.2) AL21(14.4,-21.2) AL23(16,-21.2) AL25(17.6,-21.2) AL27(19.2,-21.2) AM5(1.6,-21.6) AM6(2.4,-21.6) AM8(4,-21.6) AM10(5.6,-21.6) AM12(7.2,-21.6) AM14(8.8,-21.6) AM16(10.4,-21.6) AM18(12,-21.6) AM20(13.6,-21.6) AM22(15.2,-21.6) AM24(16.8,-21.6) AM26(18.4,-21.6) AM28(20,-21.6) B6(2.4,-0.4) B8(4,-0.4) B10(5.6,-0.4) B12(7.2,-0.4) B14(8.8,-0.4) B16(10.4,-0.4) B18(12,-0.4) B20(13.6,-0.4) B22(15.2,-0.4) B24(16.8,-0.4) B26(18.4,-0.4) C5(1.6,-0.8) C7(3.2,-0.8) C9(4.8,-0.8) C11(6.4,-0.8) C13(8,-0.8) C15(9.6,-0.8) C17(11.2,-0.8) C19(12.8,-0.8) C21(14.4,-0.8) C23(16,-0.8) C25(17.6,-0.8) C27(19.2,-0.8) C28(20,-0.8) D6(2.4,-1.2) D8(4,-1.2) D10(5.6,-1.2) D12(7.2,-1.2) D14(8.8,-1.2) D16(10.4,-1.2) D18(12,-1.2) D20(13.6,-1.2) D22(15.2,-1.2) D24(16.8,-1.2) D26(18.4,-1.2) E1(0,-1.6) E3(0.8,-1.6) E5(1.6,-1.6) E7(3.2,-1.6) E9(4.8,-1.6) E11(6.4,-1.6) E13(8,-1.6) E15(9.6,-1.6) E17(11.2,-1.6) E19(12.8,-1.6) E21(14.4,-1.6) E23(16,-1.6) E25(17.6,-1.6) E27(19.2,-1.6) E28(20,-1.6) E30(20.8,-1.6) E32(21.6,-1.6) F2(0.4,-2.4) F4(1.2,-2.4) F6(2.4,-2.4) F7(3.2,-2.4) F8(4,-2.4) F9(4.8,-2.4) F10(5.6,-2.4) F11(6.4,-2.4) F12(7.2,-2.4) F13(8,-2.4) F14(8.8,-2.4) F15(9.6,-2.4) F16(10.4,-2.4) F17(11.2,-2.4) F18(12,-2.4) F19(12.8,-2.4) F20(13.6,-2.4) F21(14.4,-2.4) F22(15.2,-2.4) F23(16,-2.4) F24(16.8,-2.4) F25(17.6,-2.4) F26(18.4,-2.4) F27(19.2,-2.4) F28(20,-2.4) F30(20.8,-2.4) F32(21.6,-2.4) G1(0,-3.2) G3(0.8,-3.2) G5(1.6,-3.2) G6(2.4,-3.2) G7(3.2,-3.2) G8(4,-3.2) G9(4.8,-3.2) G10(5.6,-3.2) G23(16,-3.2) G24(16.8,-3.2) G25(17.6,-3.2) G26(18.4,-3.2) G27(19.2,-3.2) G29(20.4,-3.2) G31(21.2,-3.2) H2(0.4,-4) H4(1.2,-4) H6(2.4,-4) H7(3.2,-4) H8(4,-4) H9(4.8,-4) H10(5.6,-4) H23(16,-4) H24(16.8,-4) H25(17.6,-4) H26(18.4,-4) H27(19.2,-4) H28(20,-4) H30(20.8,-4) H32(21.6,-4) J1(0,-4.8) J3(0.8,-4.8) J5(1.6,-4.8) J6(2.4,-4.8) J7(3.2,-4.8) J8(4,-4.8) J9(4.8,-4.8) J10(5.6,-4.8) J23(16,-4.8) J24(16.8,-4.8) J25(17.6,-4.8) J26(18.4,-4.8) J27(19.2,-4.8) J29(20.4,-4.8) J31(21.2,-4.8) K2(0.4,-5.6) K4(1.2,-5.6) K6(2.4,-5.6) K7(3.2,-5.6) K8(4,-5.6) K9(4.8,-5.6) K10(5.6,-5.6) K23(16,-5.6) K24(16.8,-5.6) K25(17.6,-5.6) K26(18.4,-5.6) K27(19.2,-5.6) K28(20,-5.6) K30(20.8,-5.6) K32(21.6,-5.6) L1(0,-6.4) L3(0.8,-6.4) L5(1.6,-6.4) L6(2.4,-6.4) L27(19.2,-6.4) L29(20.4,-6.4) L31(21.2,-6.4) M2(0.4,-7.2) M4(1.2,-7.2) M6(2.4,-7.2) M27(19.2,-7.2) M28(20,-7.2) M30(20.8,-7.2) M32(21.6,-7.2) N1(0,-8) N3(0.8,-8) N5(1.6,-8) N6(2.4,-8) N27(19.2,-8) N29(20.4,-8) N31(21.2,-8) P2(0.4,-8.8) P4(1.2,-8.8) P6(2.4,-8.8) P27(19.2,-8.8) P28(20,-8.8) P30(20.8,-8.8) P32(21.6,-8.8) R1(0,-9.6) R3(0.8,-9.6) R5(1.6,-9.6) R6(2.4,-9.6) R27(19.2,-9.6) R29(20.4,-9.6) R31(21.2,-9.6) T2(0.4,-10.4) T4(1.2,-10.4) T6(2.4,-10.4) T27(19.2,-10.4) T28(20,-10.4) T30(20.8,-10.4) T32(21.6,-10.4) U1(0,-11.2) U3(0.8,-11.2) U5(1.6,-11.2) U6(2.4,-11.2) U27(19.2,-11.2) U29(20.4,-11.2) U31(21.2,-11.2) V2(0.4,-12) V4(1.2,-12) V6(2.4,-12) V27(19.2,-12) V28(20,-12) V30(20.8,-12) V32(21.6,-12) W1(0,-12.8) W3(0.8,-12.8) W5(1.6,-12.8) W6(2.4,-12.8) W27(19.2,-12.8) W29(20.4,-12.8) W31(21.2,-12.8) Y2(0.4,-13.6) Y4(1.2,-13.6) Y6(2.4,-13.6) Y27(19.2,-13.6) Y28(20,-13.6) Y30(20.8,-13.6) Y32(21.6,-13.6)
  round 0.508 smd: AA11(6.4,-14.2) AA12(7.4,-14.2) AA13(8.4,-14.2) AA15(9.4,-14.2) AA16(10.4,-14.2) AA17(11.2,-14.2) AA18(12.2,-14.2) AA20(13.2,-14.2) AA21(14.2,-14.2) AA22(15.2,-14.2) AB11(6.4,-15.2) AB12(7.4,-15.2) AB13(8.4,-15.2) AB15(9.4,-15.2) AB16(10.4,-15.2) AB17(11.2,-15.2) AB18(12.2,-15.2) AB20(13.2,-15.2) AB21(14.2,-15.2) AB22(15.2,-15.2) L11(6.4,-6.4) L12(7.4,-6.4) L13(8.4,-6.4) L15(9.4,-6.4) L16(10.4,-6.4) L17(11.2,-6.4) L18(12.2,-6.4) L20(13.2,-6.4) L21(14.2,-6.4) L22(15.2,-6.4) M11(6.4,-7.4) M12(7.4,-7.4) M13(8.4,-7.4) M15(9.4,-7.4) M16(10.4,-7.4) M17(11.2,-7.4) M18(12.2,-7.4) M20(13.2,-7.4) M21(14.2,-7.4) M22(15.2,-7.4) N11(6.4,-8.4) N12(7.4,-8.4) N13(8.4,-8.4) N15(9.4,-8.4) N16(10.4,-8.4) N17(11.2,-8.4) N18(12.2,-8.4) N20(13.2,-8.4) N21(14.2,-8.4) N22(15.2,-8.4) R11(6.4,-9.4) R12(7.4,-9.4) R13(8.4,-9.4) R15(9.4,-9.4) R16(10.4,-9.4) R17(11.2,-9.4) R18(12.2,-9.4) R20(13.2,-9.4) R21(14.2,-9.4) R22(15.2,-9.4) T11(6.4,-10.4) T12(7.4,-10.4) T13(8.4,-10.4) T15(9.4,-10.4) T16(10.4,-10.4) T17(11.2,-10.4) T18(12.2,-10.4) T20(13.2,-10.4) T21(14.2,-10.4) T22(15.2,-10.4) U11(6.4,-11.2) U12(7.4,-11.2) U13(8.4,-11.2) U15(9.4,-11.2) U16(10.4,-11.2) U17(11.2,-11.2) U18(12.2,-11.2) U20(13.2,-11.2) U21(14.2,-11.2) U22(15.2,-11.2) V11(6.4,-12.2) V12(7.4,-12.2) V13(8.4,-12.2) V15(9.4,-12.2) V16(10.4,-12.2) V17(11.2,-12.2) V18(12.2,-12.2) V20(13.2,-12.2) V21(14.2,-12.2) V22(15.2,-12.2) Y11(6.4,-13.2) Y12(7.4,-13.2) Y13(8.4,-13.2) Y15(9.4,-13.2) Y16(10.4,-13.2) Y17(11.2,-13.2) Y18(12.2,-13.2) Y20(13.2,-13.2) Y21(14.2,-13.2) Y22(15.2,-13.2)
